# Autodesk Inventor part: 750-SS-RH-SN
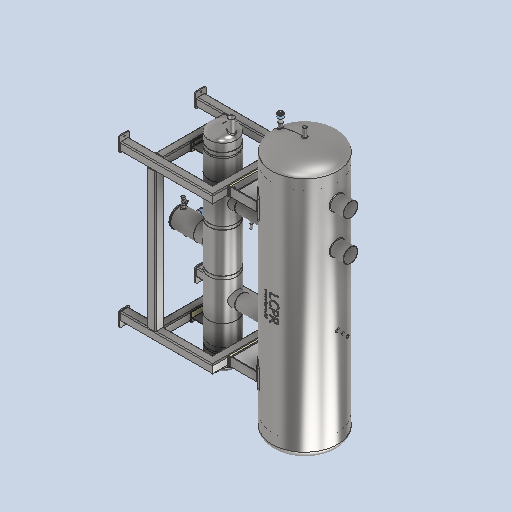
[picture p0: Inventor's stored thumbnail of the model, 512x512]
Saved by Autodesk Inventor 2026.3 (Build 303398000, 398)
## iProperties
Created: 2026-05
Part Number: 750-SS-RH-SN
Material: Generic
Document SubType Name: Modeling
Designer: rva
Density: 1 g/cm^3
Appearance: Default
Author: rva
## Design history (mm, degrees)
derived "LCPR-750-SS-RH-SN.iam"
body "Solid1"
node "LCPR-SS-750-2500-150-WELD.iam:1::750 mm-SS-Dome End Cap.ipt:"
node "LCPR-SS-750-2500-150-WELD.iam:1::750 mm-SS-Dome End Cap.ipt:"
node "LCPR-SS-750-2500-150-WELD.iam:1::H1100-R.ipt:1"
node "LCPR-SS-750-2500-150-WELD.iam:1::LCPR-750-SS-Leg-WELD.iam:1:"
node "LCPR-SS-750-2500-150-WELD.iam:1::LCPR-750-SS-Leg-WELD.iam:2:"
node "LCPR-SS-750-2500-150-WELD.iam:1::LCPR-LOGO.ipt:1"
node "LCPR-SS-750-2500-150-WELD.iam:1::Welds"
node "Sub-SS-300-150-1940-110-75-65-RH.iam:1::300-110-SS-Hole Sub "
node "Sub-SS-300-150-1940-110-75-65-RH.iam:1::300-110-SS-Hole Sub "
node "Sub-SS-300-150-1940-110-75-65-RH.iam:1::300 mm-SS-Subcooler "
node "Sub-SS-300-150-1940-110-75-65-RH.iam:1::300 mm-SS-Subcooler "
node "Sub-SS-300-150-1940-110-75-65-RH.iam:1::1-2 Inch NPT Socket "
node "Sub-SS-300-150-1940-110-75-65-RH.iam:1::Welds"
node "Sub-SS-300-150-1940-110-75-65-RH.iam:1::H1100-R_MIR.ipt:1"
node "LPR-750-Frame Assembly.iam:1::LCPR-SS-750-170 x 120 Frame Fo"
node "LPR-750-Frame Assembly.iam:1::LCPR-SS-750-170 x 120 Frame Fo"
node "LPR-750-Frame Assembly.iam:1::LCPR-SS-750-170 x 120 Frame Fo"
node "LPR-750-Frame Assembly.iam:1::LCPR-SS-750-170 x 120 Frame Fo"
node "Nylon Heat Tranfer Spacer 640x100.ipt:1"
node "Nylon Heat Tranfer Spacer 640x100.ipt:2"
node "AS 1111 - M12 x 140.ipt:1"
node "AS 1112 (4) - Metric M12:1"
node "AS 1237 (4.2) 12 mm:1"
node "AS 1237 (4.2) 12 mm:2"
node "AS 1111 - M12 x 140.ipt:2"
node "AS 1112 (4) - Metric M12:2"
node "AS 1237 (4.2) 12 mm:3"
node "AS 1237 (4.2) 12 mm:4"
node "AS 1111 - M12 x 140.ipt:3"
node "AS 1112 (4) - Metric M12:3"
node "AS 1237 (4.2) 12 mm:5"
node "AS 1237 (4.2) 12 mm:6"
node "AS 1111 - M12 x 140.ipt:4"
node "AS 1112 (4) - Metric M12:4"
node "AS 1237 (4.2) 12 mm:7"
node "AS 1237 (4.2) 12 mm:8"
node "Welds"
node "Nylon Heat Tranfer Spacer 175x100.ipt:1"
node "Nylon Heat Tranfer Spacer 175x100.ipt:2"
node "LCPR-750-SS-RH-SN.iam_Bodies"
